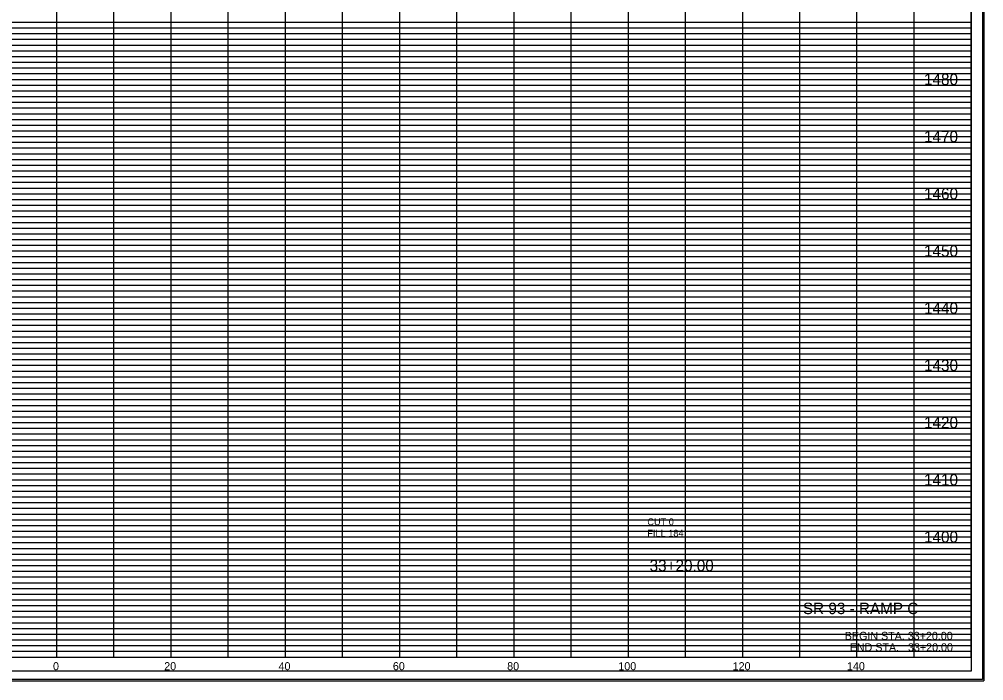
# Model space of a CAD drawing. Extents: x 980 to 2064, y 978 to 2267.
# Drawn here: x 1523.4 to 1692.2, y 1515.9 to 1631.5 of the extents above; entities that cross this region are included whole.
import ezdxf

# ---------------------------------------------------------------- set-up
doc = ezdxf.new("R2010")
doc.units = 0
for name, color, linetype in [('Default', 7, 'Continuous'), ('DESIGN - SHEET - Corner Text', 7, 'Continuous'), ('DESIGN - SHEET - Light Grid', 7, 'Continuous'), ('DESIGN - SHEET - Linework', 7, 'Continuous'), ('DESIGN - SHEET - Plot Shape', 7, 'Continuous'), ('DESIGN - TYPICAL - Text', 7, 'Continuous')]:
    doc.layers.add(name, color=color, linetype=linetype)

# ---------------------------------------------------------------- blocks, each defined once
blk = doc.blocks.new('XSTSHT')
at = {"layer": 'DESIGN - SHEET - Light Grid'}
for p, q in [((8, 11.1), (16, 11.1)), ((16, 11.1), (24, 11.1)), ((24, 11.1), (32, 11.1)), ((8, 10.9), (16, 10.9)), ((8, 10.8), (16, 10.8)), ((16, 10.9), (24, 10.9)), ((16, 10.8), (24, 10.8)), ((24, 10.9), (32, 10.9)), ((24, 10.8), (32, 10.8)), ((8, 10.7), (16, 10.7)), ((16, 10.7), (24, 10.7)), ((24, 10.7), (32, 10.7)), ((8, 10.6), (16, 10.6)), ((8, 10.5), (16, 10.5)), ((16, 10.6), (24, 10.6)), ((16, 10.5), (24, 10.5)), ((24, 10.6), (32, 10.6)), ((24, 10.5), (32, 10.5)), ((8, 10.4), (16, 10.4)), ((8, 10.3), (16, 10.3)), ((16, 10.4), (24, 10.4)), ((16, 10.3), (24, 10.3)), ((24, 10.4), (32, 10.4)), ((24, 10.3), (32, 10.3)), ((8, 10.2), (16, 10.2)), ((16, 10.2), (24, 10.2)), ((24, 10.2), (32, 10.2)), ((8, 10.1), (16, 10.1)), ((16, 10.1), (24, 10.1)), ((24, 10.1), (32, 10.1)), ((8, 9.9), (16, 9.9)), ((8, 9.8), (16, 9.8)), ((16, 9.9), (24, 9.9)), ((16, 9.8), (24, 9.8)), ((24, 9.9), (32, 9.9)), ((24, 9.8), (32, 9.8)), ((8, 9.7), (16, 9.7)), ((16, 9.7), (24, 9.7)), ((24, 9.7), (32, 9.7)), ((8, 9.6), (16, 9.6)), ((8, 9.5), (16, 9.5)), ((16, 9.6), (24, 9.6)), ((16, 9.5), (24, 9.5)), ((24, 9.6), (32, 9.6)), ((24, 9.5), (32, 9.5)), ((8, 9.4), (16, 9.4)), ((8, 9.3), (16, 9.3)), ((16, 9.4), (24, 9.4)), ((16, 9.3), (24, 9.3)), ((24, 9.4), (32, 9.4)), ((24, 9.3), (32, 9.3)), ((8, 9.2), (16, 9.2)), ((16, 9.2), (24, 9.2)), ((24, 9.2), (32, 9.2)), ((8, 9.1), (16, 9.1)), ((16, 9.1), (24, 9.1)), ((24, 9.1), (32, 9.1)), ((8, 8.9), (16, 8.9)), ((8, 8.8), (16, 8.8)), ((16, 8.9), (24, 8.9)), ((16, 8.8), (24, 8.8)), ((24, 8.9), (32, 8.9)), ((24, 8.8), (32, 8.8)), ((8, 8.7), (16, 8.7)), ((16, 8.7), (24, 8.7)), ((24, 8.7), (32, 8.7)), ((8, 8.6), (16, 8.6)), ((8, 8.5), (16, 8.5)), ((16, 8.6), (24, 8.6)), ((16, 8.5), (24, 8.5)), ((24, 8.6), (32, 8.6)), ((24, 8.5), (32, 8.5)), ((8, 8.4), (16, 8.4)), ((8, 8.3), (16, 8.3)), ((16, 8.4), (24, 8.4)), ((16, 8.3), (24, 8.3)), ((24, 8.4), (32, 8.4)), ((24, 8.3), (32, 8.3)), ((8, 8.2), (16, 8.2)), ((8, 8.1), (16, 8.1)), ((16, 8.2), (24, 8.2)), ((16, 8.1), (24, 8.1)), ((24, 8.2), (32, 8.2)), ((24, 8.1), (32, 8.1)), ((8, 7.9), (16, 7.9)), ((8, 7.8), (16, 7.8)), ((16, 7.9), (24, 7.9)), ((16, 7.8), (24, 7.8)), ((24, 7.9), (32, 7.9)), ((24, 7.8), (32, 7.8)), ((8, 7.7), (16, 7.7)), ((8, 7.6), (16, 7.6)), ((16, 7.7), (24, 7.7)), ((16, 7.6), (24, 7.6)), ((24, 7.7), (32, 7.7)), ((24, 7.6), (32, 7.6)), ((8, 7.5), (16, 7.5)), ((16, 7.5), (24, 7.5)), ((24, 7.5), (32, 7.5)), ((8, 7.4), (16, 7.4)), ((8, 7.3), (16, 7.3)), ((16, 7.4), (24, 7.4)), ((16, 7.3), (24, 7.3)), ((24, 7.4), (32, 7.4)), ((24, 7.3), (32, 7.3)), ((8, 7.2), (16, 7.2)), ((8, 7.1), (16, 7.1)), ((16, 7.2), (24, 7.2)), ((16, 7.1), (24, 7.1)), ((24, 7.2), (32, 7.2)), ((24, 7.1), (32, 7.1)), ((8, 6.9), (16, 6.9)), ((8, 6.8), (16, 6.8)), ((16, 6.9), (24, 6.9)), ((16, 6.8), (24, 6.8)), ((24, 6.9), (32, 6.9)), ((24, 6.8), (32, 6.8)), ((8, 6.7), (16, 6.7)), ((8, 6.6), (16, 6.6)), ((16, 6.7), (24, 6.7)), ((16, 6.6), (24, 6.6)), ((24, 6.7), (32, 6.7)), ((24, 6.6), (32, 6.6)), ((8, 6.5), (16, 6.5)), ((16, 6.5), (24, 6.5)), ((24, 6.5), (32, 6.5)), ((8, 6.4), (16, 6.4)), ((8, 6.3), (16, 6.3)), ((16, 6.4), (24, 6.4)), ((16, 6.3), (24, 6.3)), ((24, 6.4), (32, 6.4)), ((24, 6.3), (32, 6.3)), ((8, 6.2), (16, 6.2)), ((8, 6.1), (16, 6.1)), ((16, 6.2), (24, 6.2)), ((16, 6.1), (24, 6.1)), ((24, 6.2), (32, 6.2)), ((24, 6.1), (32, 6.1)), ((8, 5.9), (16, 5.9)), ((8, 5.8), (16, 5.8)), ((16, 5.9), (24, 5.9)), ((16, 5.8), (24, 5.8)), ((24, 5.9), (32, 5.9)), ((24, 5.8), (32, 5.8)), ((8, 5.7), (16, 5.7)), ((8, 5.6), (16, 5.6)), ((16, 5.7), (24, 5.7)), ((16, 5.6), (24, 5.6)), ((24, 5.7), (32, 5.7)), ((24, 5.6), (32, 5.6)), ((8, 5.5), (16, 5.5)), ((8, 5.4), (16, 5.4)), ((16, 5.5), (24, 5.5)), ((16, 5.4), (24, 5.4)), ((24, 5.5), (32, 5.5)), ((24, 5.4), (32, 5.4)), ((8, 5.3), (16, 5.3)), ((16, 5.3), (24, 5.3)), ((24, 5.3), (32, 5.3)), ((8, 5.2), (16, 5.2)), ((8, 5.1), (16, 5.1)), ((16, 5.2), (24, 5.2)), ((16, 5.1), (24, 5.1)), ((24, 5.2), (32, 5.2)), ((24, 5.1), (32, 5.1)), ((8, 4.9), (16, 4.9)), ((16, 4.9), (24, 4.9)), ((24, 4.9), (32, 4.9)), ((8, 4.8), (16, 4.8)), ((16, 4.8), (24, 4.8)), ((24, 4.8), (32, 4.8)), ((8, 4.7), (16, 4.7)), ((8, 4.6), (16, 4.6)), ((16, 4.7), (24, 4.7)), ((16, 4.6), (24, 4.6)), ((24, 4.7), (32, 4.7)), ((24, 4.6), (32, 4.6)), ((8, 4.5), (16, 4.5)), ((8, 4.4), (16, 4.4)), ((16, 4.5), (24, 4.5)), ((16, 4.4), (24, 4.4)), ((24, 4.5), (32, 4.5)), ((24, 4.4), (32, 4.4)), ((8, 4.3), (16, 4.3)), ((16, 4.3), (24, 4.3)), ((24, 4.3), (32, 4.3)), ((8, 4.2), (16, 4.2)), ((8, 4.1), (16, 4.1)), ((16, 4.2), (24, 4.2)), ((16, 4.1), (24, 4.1)), ((24, 4.2), (32, 4.2)), ((24, 4.1), (32, 4.1)), ((8, 3.9), (16, 3.9)), ((16, 3.9), (24, 3.9)), ((24, 3.9), (32, 3.9)), ((8, 3.8), (16, 3.8)), ((16, 3.8), (24, 3.8)), ((24, 3.8), (32, 3.8)), ((8, 3.7), (16, 3.7)), ((8, 3.6), (16, 3.6)), ((16, 3.7), (24, 3.7)), ((16, 3.6), (24, 3.6)), ((24, 3.7), (32, 3.7)), ((24, 3.6), (32, 3.6)), ((8, 3.5), (16, 3.5)), ((8, 3.4), (16, 3.4)), ((16, 3.5), (24, 3.5)), ((16, 3.4), (24, 3.4)), ((24, 3.5), (32, 3.5)), ((24, 3.4), (32, 3.4)), ((8, 3.3), (16, 3.3)), ((16, 3.3), (24, 3.3)), ((24, 3.3), (32, 3.3)), ((8, 3.2), (16, 3.2)), ((8, 3.1), (16, 3.1)), ((16, 3.2), (24, 3.2)), ((16, 3.1), (24, 3.1)), ((24, 3.2), (32, 3.2)), ((24, 3.1), (32, 3.1)), ((8, 2.9), (16, 2.9)), ((16, 2.9), (24, 2.9)), ((24, 2.9), (32, 2.9)), ((8, 2.8), (16, 2.8)), ((8, 2.7), (16, 2.7)), ((16, 2.8), (24, 2.8)), ((16, 2.7), (24, 2.7)), ((24, 2.8), (32, 2.8)), ((24, 2.7), (32, 2.7)), ((8, 2.6), (16, 2.6)), ((16, 2.6), (24, 2.6)), ((24, 2.6), (32, 2.6)), ((8, 2.5), (16, 2.5)), ((8, 2.4), (16, 2.4)), ((16, 2.5), (24, 2.5)), ((16, 2.4), (24, 2.4)), ((24, 2.5), (32, 2.5)), ((24, 2.4), (32, 2.4)), ((8, 2.3), (16, 2.3)), ((8, 2.2), (16, 2.2)), ((16, 2.3), (24, 2.3)), ((16, 2.2), (24, 2.2)), ((24, 2.3), (32, 2.3)), ((24, 2.2), (32, 2.2)), ((8, 2.1), (16, 2.1)), ((16, 2.1), (24, 2.1)), ((24, 2.1), (32, 2.1)), ((8, 1.9), (16, 1.9)), ((16, 1.9), (24, 1.9)), ((24, 1.9), (32, 1.9)), ((8, 1.8), (16, 1.8)), ((8, 1.7), (16, 1.7)), ((16, 1.8), (24, 1.8)), ((16, 1.7), (24, 1.7)), ((24, 1.8), (32, 1.8)), ((24, 1.7), (32, 1.7)), ((8, 1.6), (16, 1.6)), ((16, 1.6), (24, 1.6)), ((24, 1.6), (32, 1.6)), ((8, 1.5), (16, 1.5)), ((8, 1.4), (16, 1.4)), ((16, 1.5), (24, 1.5)), ((16, 1.4), (24, 1.4)), ((24, 1.5), (32, 1.5)), ((24, 1.4), (32, 1.4)), ((8, 1.3), (16, 1.3)), ((8, 1.2), (16, 1.2)), ((16, 1.3), (24, 1.3)), ((16, 1.2), (24, 1.2)), ((24, 1.3), (32, 1.3)), ((24, 1.2), (32, 1.2)), ((8, 1.1), (16, 1.1)), ((16, 1.1), (24, 1.1)), ((24, 1.1), (32, 1.1)), ((8, 0.9), (16, 0.9)), ((16, 0.9), (24, 0.9)), ((24, 0.9), (32, 0.9)), ((8, 0.8), (16, 0.8)), ((8, 0.7), (16, 0.7)), ((16, 0.8), (24, 0.8)), ((16, 0.7), (24, 0.7)), ((24, 0.8), (32, 0.8)), ((24, 0.7), (32, 0.7)), ((8, 0.6), (16, 0.6)), ((16, 0.6), (24, 0.6)), ((24, 0.6), (32, 0.6)), ((8, 0.5), (16, 0.5)), ((8, 0.4), (16, 0.4)), ((16, 0.5), (24, 0.5)), ((16, 0.4), (24, 0.4)), ((24, 0.5), (32, 0.5)), ((24, 0.4), (32, 0.4)), ((8, 0.3), (16, 0.3)), ((8, 0.2), (16, 0.2)), ((16, 0.3), (24, 0.3)), ((16, 0.2), (24, 0.2)), ((24, 0.3), (32, 0.3)), ((24, 0.2), (32, 0.2)), ((8, 0.1), (16, 0.1)), ((16, 0.1), (24, 0.1)), ((24, 0.1), (32, 0.1))]:
    blk.add_line(p, q, dxfattribs=at)
at = {"layer": 'DESIGN - SHEET - Linework'}
for p, q in [((32.217, 21.414), (32.217, -0.414)), ((16, 0), (16, 21)), ((17, 0), (17, 21)), ((18, 0), (18, 21)), ((19, 0), (19, 21)), ((20, 0), (20, 21)), ((21, 0), (21, 21)), ((22, 0), (22, 21)), ((23, 0), (23, 21)), ((24, 0), (24, 21)), ((25, 0), (25, 21)), ((26, 0), (26, 21)), ((27, 0), (27, 21)), ((28, 0), (28, 20)), ((29, 0), (29, 20)), ((30, 0), (30, 20)), ((31, 0), (31, 20)), ((0, 11), (32, 11)), ((0, 10), (32, 10)), ((0, 9), (32, 9)), ((0, 8), (32, 8)), ((0, 7), (32, 7)), ((0, 6), (32, 6)), ((0, 5), (32, 5)), ((0, 4), (32, 4)), ((0, 3), (32, 3)), ((0, 2), (32, 2)), ((0, 1), (32, 1)), ((-1.823, -0.414), (32.217, -0.414))]:
    blk.add_line(p, q, dxfattribs=at)
blk.add_lwpolyline([(0, 21), (0, 0), (32, 0), (32, 21), (0, 21)], dxfattribs=at)
at = {"layer": 'DESIGN - SHEET - Plot Shape'}
for points in [[(-1.803, 21.394), (32.197, 21.394), (32.197, -0.394), (-1.803, -0.394)], [(-0.85, 21), (32, 21), (32, -0.25), (-0.85, -0.25)]]:
    blk.add_lwpolyline(points, close=True, dxfattribs=at)

msp = doc.modelspace()

# ---------------------------------------------------------------- block references
at = {"layer": 'Default', "xscale": 10, "yscale": 10}
msp.add_blockref('XSTSHT', (1370, 1520), dxfattribs=at)

# ---------------------------------------------------------------- texts
at = {"layer": 'Default'}
for s, height, p in [('     1480     ', 2, (1678.01, 1620)), ('     1470     ', 2, (1678.01, 1610)), ('     1460     ', 2, (1678.01, 1600)), ('     1450     ', 2, (1678.01, 1590)), ('     1440     ', 2, (1678.01, 1580)), ('     1430     ', 2, (1678.01, 1570)), ('     1420     ', 2, (1678.01, 1560)), ('     1410     ', 2, (1678.01, 1550)), ('     1400     ', 2, (1678.01, 1540)), ('     33+20.00     ', 2, (1630, 1534.99)), ('     0     ', 1.4, (1526.74, 1517.7)), ('     0     ', 1.4, (1526.74, 1517.7)), ('     20     ', 1.4, (1546.2, 1517.7)), ('     40     ', 1.4, (1566.2, 1517.7)), ('     60     ', 1.4, (1586.2, 1517.7)), ('     80     ', 1.4, (1606.2, 1517.7)), ('     100     ', 1.4, (1625.65, 1517.7)), ('     120     ', 1.4, (1645.65, 1517.7)), ('     140     ', 1.4, (1665.65, 1517.7))]:
    msp.add_text(s, height=height, dxfattribs=at).set_placement(p)
at = {"layer": 'DESIGN - SHEET - Corner Text'}
for s, height, p in [('SR 93 - RAMP C', 2, (1660.53, 1527.5)), ('BEGIN STA. 33+20.00', 1.4, (1667.86, 1523)), ('END STA.   33+20.00', 1.4, (1668.73, 1521))]:
    msp.add_text(s, height=height, dxfattribs=at).set_placement(p)
at = {"layer": 'DESIGN - TYPICAL - Text'}
for s, p in [('CUT 0', (1633.32, 1543.05)), ('FILL 184', (1633.32, 1541.05))]:
    msp.add_text(s, height=1.2, dxfattribs=at).set_placement(p)

doc.saveas('drawing.dxf')
